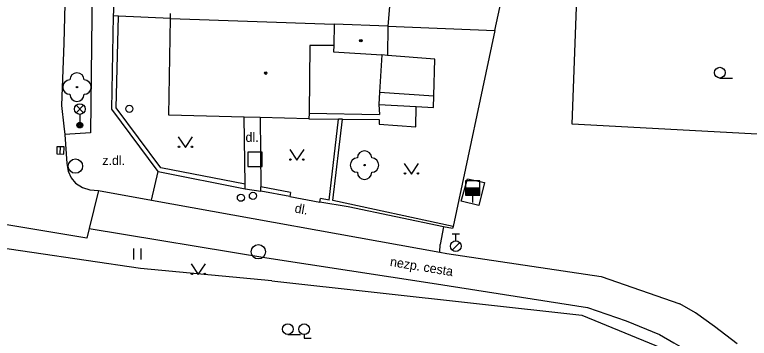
# Model space of a CAD drawing. Extents: x -596024 to -594475, y -1163820 to -1161957.
# Drawn here: x -595804.3 to -595752.9, y -1163071.7 to -1163049 of the extents above; entities that cross this region are included whole.
import ezdxf

# ---------------------------------------------------------------- set-up
doc = ezdxf.new("R2010")
doc.units = 0
for name, color, linetype in [('Level 10', 7, 'Continuous'), ('Level 11', 7, 'Continuous'), ('Level 22', 7, 'Continuous'), ('Level 26', 7, 'Continuous'), ('Level 27', 7, 'Continuous'), ('Level 28', 7, 'Continuous'), ('Level 33', 7, 'Continuous'), ('Level 36', 7, 'Continuous'), ('Level 39', 7, 'Continuous'), ('Level 40', 7, 'Continuous'), ('Level 5', 7, 'Continuous'), ('Level 7', 7, 'Continuous'), ('Level 8', 7, 'Continuous')]:
    doc.layers.add(name, color=color, linetype=linetype)

msp = doc.modelspace()

# ---------------------------------------------------------------- linework, layer by layer
at = {"layer": 'Level 10'}
for points in [[(-595800.46, -1163034.82), (-595800.62, -1163042.8), (-595800.83, -1163051.01)], [(-595799.22, -1163064.66), (-595815.57, -1163061.92), (-595840.13, -1163056.57), (-595859.05, -1163051.93), (-595867.53, -1163049.42)], [(-595800.83, -1163051.01), (-595800.99, -1163055.37), (-595800.82, -1163056.83), (-595800.76, -1163057.4)], [(-595800.76, -1163057.4), (-595800.62, -1163059.44), (-595800.53, -1163059.98), (-595800.32, -1163060.44), (-595800.02, -1163060.81), (-595799.52, -1163061.11), (-595799.01, -1163061.28), (-595798.41, -1163061.33)], [(-595798.41, -1163061.33), (-595799.06, -1163063.99), (-595799.22, -1163064.66)]]:
    msp.add_lwpolyline(points, dxfattribs=at)
at = {"layer": 'Level 11'}
for points in [[(-595798.71, -1163034.87), (-595798.96, -1163057.29), (-595800.76, -1163057.4)], [(-595770.71, -1163050.13), (-595769.25, -1163043.46)], [(-595797, -1163049.12), (-595797.35, -1163049.1)], [(-595793.38, -1163049.3), (-595797, -1163049.12)], [(-595778.18, -1163049.83), (-595770.71, -1163050.13)], [(-595778.61, -1163051.84), (-595778.77, -1163054.45)], [(-595774.96, -1163054.7), (-595774.89, -1163052.14), (-595778.21, -1163051.87)], [(-595778.77, -1163054.45), (-595778.8, -1163055.31)], [(-595778.77, -1163054.45), (-595774.96, -1163054.7)], [(-595776.21, -1163055.45), (-595774.98, -1163055.52), (-595774.96, -1163054.7)], [(-595778.8, -1163055.31), (-595776.21, -1163055.45)], [(-595778.8, -1163055.31), (-595778.76, -1163056.01)], [(-595778.79, -1163056.36), (-595778.79, -1163056.69), (-595776.22, -1163056.88), (-595776.21, -1163055.45)], [(-595788.16, -1163060.89), (-595788.23, -1163056.19)], [(-595787.11, -1163056.22), (-595787.05, -1163061.07)], [(-595783.7, -1163056.31), (-595781.62, -1163056.33)], [(-595783.69, -1163055.91), (-595778.76, -1163056.01)], [(-595781.35, -1163056.33), (-595781.62, -1163056.33)], [(-595781.35, -1163056.33), (-595778.79, -1163056.36)], [(-595794.71, -1163062.01), (-595794.23, -1163060)], [(-595772.6, -1163060.5), (-595771.43, -1163060.77), (-595771.83, -1163062.38), (-595773.06, -1163062.07), (-595772.6, -1163060.5)], [(-595798.41, -1163061.33), (-595794.71, -1163062.01)], [(-595794.71, -1163062.01), (-595774.55, -1163065.64)], [(-595799.06, -1163063.99), (-595786.65, -1163066.03)], [(-595774.29, -1163063.86), (-595774.53, -1163065.1)], [(-595774.55, -1163065.64), (-595774.53, -1163065.1)], [(-595786.65, -1163066.03), (-595775.08, -1163067.8), (-595764.22, -1163069.5), (-595761.52, -1163070.45), (-595759.2, -1163071.4), (-595758.18, -1163071.99), (-595757.54, -1163072.35), (-595756.49, -1163073.25), (-595755.73, -1163074.15), (-595755.31, -1163074.81), (-595754.91, -1163075.51)], [(-595774.55, -1163065.64), (-595774.05, -1163065.72), (-595763.26, -1163067.34), (-595757.77, -1163069.26)], [(-595786.29, -1163067.64), (-595764.61, -1163070.04), (-595758.22, -1163072.67)], [(-595753.76, -1163072.04), (-595755.35, -1163070.83), (-595756.68, -1163069.88), (-595757.77, -1163069.26)]]:
    msp.add_lwpolyline(points, dxfattribs=at)
at = {"layer": 'Level 22'}
for centre in [(-595799.91, -1163054.09), (-595779.81, -1163059.55)]:
    msp.add_circle(centre, 0.05, dxfattribs=at)
for centre, start, end in [((-595799.91, -1163053.59), 0, 180), ((-595800.41, -1163054.09), 90, 270), ((-595799.41, -1163054.09), 270, 90), ((-595799.91, -1163054.59), 180, 0), ((-595779.81, -1163059.05), 0, 180), ((-595780.31, -1163059.55), 90, 270), ((-595779.31, -1163059.55), 270, 90), ((-595779.81, -1163060.05), 180, 0)]:
    msp.add_arc(centre, 0.5, start, end, dxfattribs=at)
at = {"layer": 'Level 26'}
msp.add_lwpolyline([(-595787.97, -1163059.64), (-595786.97, -1163059.64), (-595786.97, -1163058.64), (-595787.97, -1163058.64)], close=True, dxfattribs=at)
at = {"layer": 'Level 27'}
msp.add_line((-595801.075, -1163058.77), (-595801.065, -1163058.27), dxfattribs=at)
msp.add_lwpolyline([(-595800.825, -1163058.775), (-595800.815, -1163058.275), (-595801.315, -1163058.265), (-595801.325, -1163058.765)], close=True, dxfattribs=at)
for centre in [(-595800.02, -1163059.62), (-595787.23, -1163065.61)]:
    msp.add_circle(centre, 0.5, dxfattribs=at)
at = {"layer": 'Level 28'}
for p, q in [((-595772.76, -1163061.14), (-595771.76, -1163061.14)), ((-595772.76, -1163061.19), (-595771.76, -1163061.19)), ((-595772.76, -1163061.24), (-595771.76, -1163061.24)), ((-595772.76, -1163061.29), (-595771.76, -1163061.29)), ((-595772.76, -1163061.34), (-595771.76, -1163061.34)), ((-595772.76, -1163061.39), (-595771.76, -1163061.39)), ((-595772.76, -1163061.44), (-595771.76, -1163061.44)), ((-595772.76, -1163061.49), (-595771.76, -1163061.49)), ((-595772.76, -1163061.54), (-595771.76, -1163061.54)), ((-595772.76, -1163061.59), (-595771.76, -1163061.59)), ((-595772.26, -1163061.64), (-595772.26, -1163062.17)), ((-595773.68, -1163064.345), (-595773.18, -1163064.345)), ((-595773.43, -1163064.845), (-595773.43, -1163064.345)), ((-595773.688, -1163065.492), (-595773.158, -1163064.962))]:
    msp.add_line(p, q, dxfattribs=at)
msp.add_lwpolyline([(-595772.76, -1163061.64), (-595771.76, -1163061.64), (-595771.76, -1163060.64), (-595772.76, -1163060.64)], close=True, dxfattribs=at)
for centre, radius in [((-595796.25, -1163055.61), 0.25), ((-595787.61, -1163061.7), 0.25), ((-595788.45, -1163061.83), 0.25), ((-595773.43, -1163065.22), 0.375)]:
    msp.add_circle(centre, radius, dxfattribs=at)
at = {"layer": 'Level 33'}
for p, q in [((-595799.975, -1163055.89), (-595799.445, -1163055.36)), ((-595799.975, -1163055.36), (-595799.445, -1163055.89)), ((-595799.71, -1163056), (-595799.71, -1163056.75))]:
    msp.add_line(p, q, dxfattribs=at)
for centre, radius in [((-595799.71, -1163055.625), 0.375), ((-595799.71, -1163056.75), 0.2), ((-595799.71, -1163056.75), 0.145), ((-595799.71, -1163056.75), 0.0876)]:
    msp.add_circle(centre, radius, dxfattribs=at)
at = {"layer": 'Level 36'}
for p, q in [((-595754.97, -1163053.455), (-595754.095, -1163053.455)), ((-595795.934, -1163066.143), (-595795.934, -1163065.393)), ((-595795.434, -1163066.143), (-595795.434, -1163065.393)), ((-595785.17, -1163071.395), (-595784.295, -1163071.395))]:
    msp.add_line(p, q, dxfattribs=at)
for points in [[(-595792.83, -1163057.57), (-595792.33, -1163058.32), (-595791.83, -1163057.57)], [(-595785.04, -1163058.46), (-595784.54, -1163059.21), (-595784.04, -1163058.46)], [(-595777.03, -1163059.43), (-595776.53, -1163060.18), (-595776.03, -1163059.43)], [(-595791.93, -1163066.46), (-595791.43, -1163067.21), (-595790.93, -1163066.46)], [(-595784.03, -1163071.405), (-595784.03, -1163071.655), (-595783.53, -1163071.655)]]:
    msp.add_lwpolyline(points, dxfattribs=at)
for centre, radius in [((-595754.97, -1163053.08), 0.375), ((-595792.78, -1163058.27), 0.05), ((-595791.881, -1163058.27), 0.05), ((-595784.99, -1163059.16), 0.05), ((-595784.091, -1163059.16), 0.05), ((-595776.98, -1163060.13), 0.05), ((-595776.081, -1163060.13), 0.05), ((-595791.88, -1163067.16), 0.05), ((-595790.981, -1163067.16), 0.05), ((-595785.17, -1163071.02), 0.375), ((-595784.03, -1163071.03), 0.375)]:
    msp.add_circle(centre, radius, dxfattribs=at)
at = {"layer": 'Level 39'}
for centre, radius in [((-595780.07, -1163050.84), 0.09), ((-595780.07, -1163050.84), 0.0398), ((-595786.72, -1163053.11), 0.09), ((-595786.72, -1163053.11), 0.0398)]:
    msp.add_circle(centre, radius, dxfattribs=at)
at = {"layer": 'Level 5'}
for points in [[(-595778, -1163047.59), (-595778.18, -1163049.83)], [(-595793.38, -1163049.3), (-595793.37, -1163048.95)], [(-595793.5, -1163056.05), (-595793.38, -1163049.3)], [(-595793.38, -1163049.3), (-595781.94, -1163049.69)], [(-595781.94, -1163049.69), (-595781.96, -1163051.18)], [(-595778.18, -1163049.83), (-595781.94, -1163049.69)], [(-595778.18, -1163049.83), (-595778.21, -1163051.87)], [(-595783.63, -1163051.17), (-595783.69, -1163055.91)], [(-595781.96, -1163051.18), (-595783.63, -1163051.17)], [(-595781.96, -1163051.18), (-595781.99, -1163051.62)], [(-595781.99, -1163051.62), (-595778.61, -1163051.84)], [(-595778.21, -1163051.87), (-595778.61, -1163051.84)], [(-595788.23, -1163056.19), (-595793.5, -1163056.05)], [(-595787.11, -1163056.22), (-595788.23, -1163056.19)], [(-595783.7, -1163056.31), (-595787.11, -1163056.22)], [(-595783.69, -1163055.91), (-595783.7, -1163056.31)]]:
    msp.add_lwpolyline(points, dxfattribs=at)
at = {"layer": 'Level 7'}
for points in [[(-595749.33, -1163057.54), (-595765.3, -1163056.68), (-595764.57, -1163037.17)], [(-595797.35, -1163049.1), (-595797.34, -1163048.75), (-595797.33, -1163047.75)], [(-595794.23, -1163060), (-595797.48, -1163055.64), (-595797.35, -1163049.1)], [(-595788.16, -1163060.89), (-595794.06, -1163059.73), (-595797.18, -1163055.54), (-595797, -1163049.12)], [(-595770.71, -1163050.13), (-595773.62, -1163063.84)], [(-595782.29, -1163061.99), (-595781.62, -1163056.33)], [(-595773.62, -1163063.84), (-595782.02, -1163062.02), (-595781.35, -1163056.33)], [(-595794.23, -1163060), (-595788.16, -1163061.2)], [(-595788.16, -1163061.2), (-595788.16, -1163060.89)], [(-595784.98, -1163061.46), (-595787.05, -1163061.07)], [(-595787.05, -1163061.38), (-595787.05, -1163061.07)], [(-595785.03, -1163061.75), (-595787.05, -1163061.38)], [(-595784.98, -1163061.46), (-595785.03, -1163061.75)], [(-595782.93, -1163062.13), (-595782.89, -1163061.89)], [(-595782.29, -1163061.99), (-595782.89, -1163061.89)], [(-595774.29, -1163063.86), (-595780.95, -1163062.46), (-595782.93, -1163062.13)], [(-595795.48, -1163066.79), (-595814.48, -1163063.99)], [(-595773.62, -1163063.84), (-595773.65, -1163063.99), (-595774.29, -1163063.86)], [(-595786.29, -1163067.64), (-595795.48, -1163066.79)]]:
    msp.add_lwpolyline(points, dxfattribs=at)
at = {"layer": 'Level 8'}
for points in [[(-595788.16, -1163061.2), (-595787.05, -1163061.38)], [(-595785.03, -1163061.75), (-595782.93, -1163062.13)]]:
    msp.add_lwpolyline(points, dxfattribs=at)

# ---------------------------------------------------------------- texts
at = {"layer": 'Level 40'}
for s, p in [('dl.', (-595788.13, -1163057.92)), ('z.dl.', (-595798.14, -1163059.54))]:
    msp.add_text(s, height=0.65, dxfattribs=at).set_placement(p)
for s, rotation, p in [('dl.', 350, (-595784.73, -1163062.86)), ('nezp. cesta', 350.665, (-595778.06, -1163066.6))]:
    msp.add_text(s, height=0.65, rotation=rotation, dxfattribs=at).set_placement(p)

doc.saveas('drawing.dxf')
